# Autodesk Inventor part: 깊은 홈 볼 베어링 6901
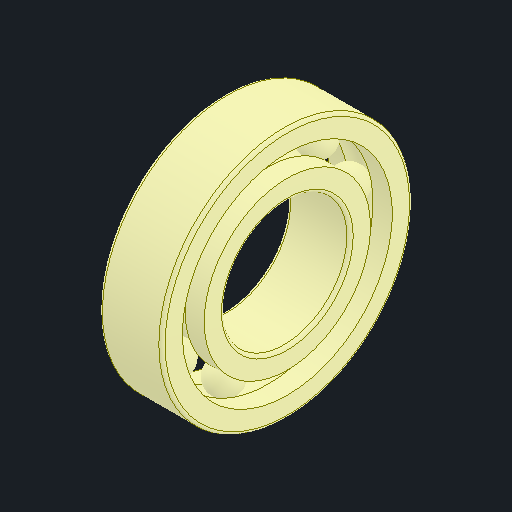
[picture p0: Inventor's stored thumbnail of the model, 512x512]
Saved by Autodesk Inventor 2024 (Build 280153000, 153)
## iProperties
Created: 2024-05
Part Number: 깊은 홈 볼 베어링 6901
Material: 강철, 연강
Description: 깊은 그루브 볼 베어링
Document SubType Name: Modeling
Designer: kh_501
Density: 7.85 g/cm^3
Appearance: 기본값
Sending System: Autodesk Inventor 2025
Preprocessor: ST-DEVELOPER v20
Author: jhkim
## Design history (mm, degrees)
feature "Solid1"
feature "Solid1:1"
feature "Solid1:2"
feature "Solid1:3"
feature "Solid1:4"
feature "Solid1:5"
feature "Solid1:6"
feature "Solid1:7"
feature "Solid1:8"
feature "Solid1:9"
feature "Solid1:10"
node "솔리드1"
node "솔리드2"
node "솔리드3"
node "솔리드4"
node "솔리드5"
node "솔리드6"
node "솔리드7"
node "솔리드8"
node "솔리드9"
node "솔리드10"
node "솔리드11"
